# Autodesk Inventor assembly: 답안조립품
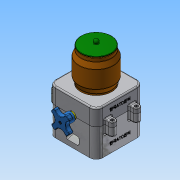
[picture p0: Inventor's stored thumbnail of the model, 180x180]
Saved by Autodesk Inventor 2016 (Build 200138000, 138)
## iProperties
Created: 2018-01
Part Number: 답안조립품
Material: 일반
Document SubType Name: Assembly
Designer: Administrator
Author: Administrator
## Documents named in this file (9)
- C:\Users\Administrator\Desktop\480108V1017\답안조립품.iam
- C:\Users\Administrator\Desktop\480108V1017\본체.ipt
- C:\Users\Administrator\Desktop\480108V1017\핸들축.ipt
- C:\Users\Administrator\Desktop\480108V1017\핸들.ipt
- C:\Users\Administrator\Desktop\480108V1017\볼트 M3x12.ipt
- C:\Users\Administrator\Desktop\480108V1017\본체커버.ipt
- C:\Users\Administrator\Desktop\480108V1017\볼트 M4x12.ipt
- C:\Users\Administrator\Desktop\480108V1017\용기.ipt
- C:\Users\Administrator\Desktop\480108V1017\용기캡.ipt
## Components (2 placed, 2 different names)
1. 핸들축:1
2. 핸들:1
